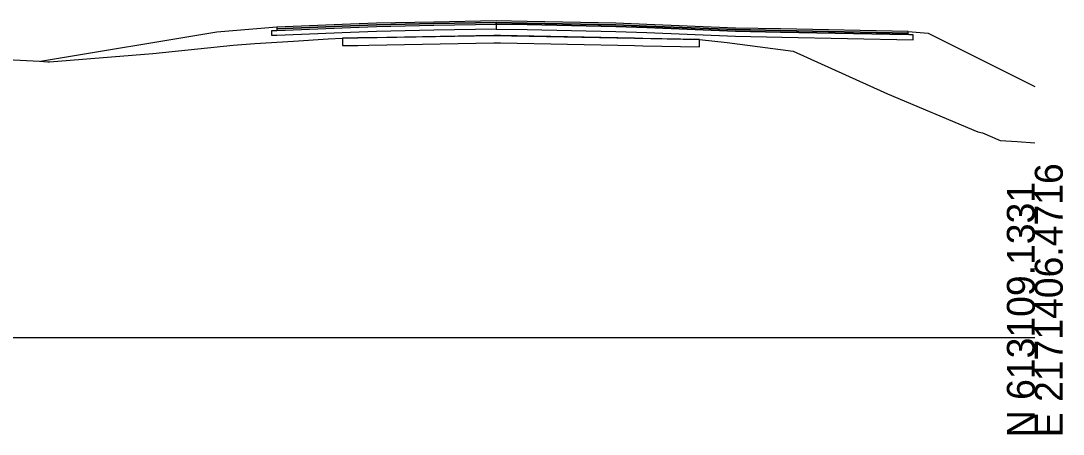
# Model space of a CAD drawing. Extents: x -26 to 1303, y -3010 to 12038.
# Drawn here: x 198.4 to 302.8, y 4490.3 to 4531.8 of the extents above; entities that cross this region are included whole.
import ezdxf

# ---------------------------------------------------------------- set-up
doc = ezdxf.new("R2010")
doc.units = 0
for name, color, linetype in [('RD_GPK_XS_Cell', 7, 'Continuous'), ('RD_XS_Base', 7, 'Continuous'), ('RD_XS_ExGround', 7, 'Continuous'), ('RD_XS_ExPaveRet', 7, 'Continuous'), ('RD_XS_Greenside', 7, 'Continuous'), ('RD_XS_Pave', 7, 'Continuous'), ('RD_XS_PaveOvlay_CP', 7, 'Continuous'), ('RD_XS_TieSlope', 7, 'Continuous')]:
    doc.layers.add(name, color=color, linetype=linetype)

msp = doc.modelspace()

# ---------------------------------------------------------------- linework, layer by layer
at = {"layer": 'RD_GPK_XS_Cell'}
msp.add_line((150, 4500), (300, 4500), dxfattribs=at)
at = {"layer": 'RD_XS_Base'}
for p, q in [((223.5, 4530.79), (223.87, 4530.81)), ((223.5, 4530.66), (223.5, 4530.79)), ((223.5, 4530.29), (223.5, 4530.66)), ((223.87, 4530.81), (224, 4530.81)), ((224, 4530.81), (231.4, 4531.11)), ((231.4, 4531.11), (234, 4531.21)), ((234, 4530.71), (231.4, 4530.61)), ((234, 4531.21), (239.76, 4531.33)), ((239.76, 4530.83), (234, 4530.71)), ((239.76, 4531.33), (246, 4531.45)), ((246, 4530.95), (239.76, 4530.83)), ((246, 4531.57), (246, 4531.61)), ((246, 4531.61), (246, 4531.44)), ((246, 4531.45), (246, 4531.57)), ((246, 4531.45), (246, 4531.45)), ((249.12, 4531.39), (246, 4531.45)), ((246, 4531.45), (246, 4531.45)), ((246, 4531.45), (246, 4531.32)), ((246, 4531.44), (246, 4530.95)), ((246, 4531.32), (246, 4530.95)), ((246, 4530.95), (249.12, 4530.89)), ((258, 4531.21), (249.12, 4531.39)), ((249.12, 4530.89), (258, 4530.71)), ((261.12, 4531.09), (258, 4531.21)), ((258, 4530.71), (261.12, 4530.59)), ((270, 4530.73), (261.12, 4531.09)), ((274.5, 4530.64), (270, 4530.73)), ((287.3, 4530.39), (274.5, 4530.64)), ((223.87, 4530.31), (223.5, 4530.29)), ((224, 4530.31), (223.87, 4530.31)), ((231.4, 4530.61), (224, 4530.31)), ((261.12, 4530.59), (270, 4530.23)), ((270, 4530.23), (274.63, 4530.14)), ((274.63, 4530.14), (287.8, 4529.88)), ((287.43, 4530.38), (287.3, 4530.39)), ((287.8, 4530.38), (287.43, 4530.38)), ((287.8, 4530.25), (287.8, 4530.38)), ((287.8, 4529.88), (287.8, 4530.25))]:
    msp.add_line(p, q, dxfattribs=at)
at = {"layer": 'RD_XS_ExGround'}
msp.add_lwpolyline([(185.28, 4528.49), (200.23, 4527.71), (201.05, 4527.66), (201.16, 4527.66), (201.22, 4527.66), (201.24, 4527.66), (211.57, 4528.5), (219.62, 4529.33), (221.81, 4529.5), (225.67, 4529.72), (229.17, 4529.95), (230.58, 4530.04), (232.13, 4530.06), (245.77, 4530.31), (259.88, 4530.03), (266.4, 4529.9), (269.16, 4529.59), (275.76, 4528.74), (284.87, 4524.62), (285.24, 4524.46), (294.29, 4520.63), (294.75, 4520.52), (296.53, 4519.77), (298.24, 4519.68), (300, 4519.52)], dxfattribs=at)
at = {"layer": 'RD_XS_ExPaveRet'}
msp.add_line((266.4, 4529.9), (260.71, 4530.01), dxfattribs=at)
for points in [[(259.88, 4530.03), (246.42, 4530.3), (245.77, 4530.31), (233.22, 4530.08), (232.13, 4530.06), (230.58, 4530.04), (230.58, 4530.04), (230.58, 4529.98), (230.58, 4529.29), (230.58, 4529.29), (232.13, 4529.31), (233.22, 4529.33), (245.77, 4529.56), (246.42, 4529.55), (259.88, 4529.28), (260.71, 4529.26), (266.4, 4529.15), (266.4, 4529.84), (266.4, 4529.9), (260.71, 4530.01), (259.88, 4530.03)], [(233.22, 4530.08), (232.13, 4530.06), (230.58, 4530.04)], [(230.58, 4530.04), (230.58, 4529.98), (230.58, 4529.29), (232.13, 4529.31), (233.22, 4529.33), (245.77, 4529.56), (246.42, 4529.55), (259.88, 4529.28), (260.71, 4529.26), (266.4, 4529.15), (266.4, 4529.84), (266.4, 4529.9)], [(246.42, 4530.3), (245.77, 4530.31), (233.22, 4530.08)], [(260.71, 4530.01), (259.88, 4530.03), (246.42, 4530.3)]]:
    msp.add_lwpolyline(points, dxfattribs=at)
at = {"layer": 'RD_XS_Greenside'}
for p, q in [((218, 4530.65), (200.32, 4527.7)), ((289.3, 4530.54), (300, 4525.19))]:
    msp.add_line(p, q, dxfattribs=at)
at = {"layer": 'RD_XS_Pave'}
for p, q in [((246, 4531.77), (239.76, 4531.65)), ((249.12, 4531.71), (246, 4531.77)), ((258, 4531.53), (249.12, 4531.71)), ((231.4, 4531.43), (224, 4531.13)), ((231.4, 4531.27), (224, 4530.97)), ((224, 4530.97), (231.4, 4531.27)), ((224, 4531.13), (224, 4531.09)), ((224, 4530.81), (231.4, 4531.11)), ((224, 4531.09), (224, 4530.97)), ((224, 4530.97), (224, 4530.93)), ((224, 4530.93), (224, 4530.81)), ((234, 4531.53), (231.4, 4531.43)), ((234, 4531.37), (231.4, 4531.27)), ((231.4, 4531.27), (234, 4531.37)), ((231.4, 4531.11), (234, 4531.21)), ((239.76, 4531.65), (234, 4531.53)), ((239.76, 4531.49), (234, 4531.37)), ((234, 4531.37), (239.76, 4531.49)), ((234, 4531.21), (239.76, 4531.33)), ((246, 4531.61), (239.76, 4531.49)), ((239.76, 4531.49), (246, 4531.61)), ((239.76, 4531.33), (246, 4531.45)), ((246, 4531.57), (246, 4531.61)), ((246, 4531.61), (249.12, 4531.55)), ((249.12, 4531.55), (246, 4531.61)), ((246, 4531.61), (246, 4531.61)), ((246, 4531.61), (246, 4531.61)), ((246, 4531.61), (246, 4531.57)), ((246, 4531.45), (246, 4531.57)), ((246, 4531.57), (246, 4531.45)), ((246, 4531.45), (246, 4531.45)), ((246, 4531.45), (246, 4531.45)), ((246, 4531.45), (249.12, 4531.39)), ((249.12, 4531.55), (258, 4531.37)), ((258, 4531.37), (249.12, 4531.55)), ((249.12, 4531.39), (258, 4531.21)), ((261.12, 4531.41), (258, 4531.53)), ((258, 4531.37), (261.12, 4531.25)), ((261.12, 4531.25), (258, 4531.37)), ((258, 4531.21), (261.12, 4531.09)), ((270, 4531.05), (261.12, 4531.41)), ((261.12, 4531.25), (270, 4530.89)), ((270, 4530.89), (261.12, 4531.25)), ((261.12, 4531.09), (270, 4530.73)), ((274.5, 4530.96), (270, 4531.05)), ((270, 4530.89), (274.5, 4530.8)), ((274.5, 4530.8), (270, 4530.89)), ((270, 4530.73), (274.5, 4530.64)), ((287.3, 4530.7), (274.5, 4530.96)), ((274.5, 4530.8), (287.3, 4530.55)), ((287.3, 4530.55), (274.5, 4530.8)), ((274.5, 4530.64), (287.3, 4530.39)), ((287.3, 4530.66), (287.3, 4530.7)), ((287.3, 4530.55), (287.3, 4530.66)), ((287.3, 4530.5), (287.3, 4530.55)), ((287.3, 4530.39), (287.3, 4530.5))]:
    msp.add_line(p, q, dxfattribs=at)
at = {"layer": 'RD_XS_PaveOvlay_CP'}
for p, q in [((246, 4531.77), (239.76, 4531.65)), ((249.12, 4531.71), (246, 4531.77)), ((258, 4531.53), (249.12, 4531.71)), ((231.4, 4531.43), (224, 4531.13)), ((234, 4531.53), (231.4, 4531.43)), ((239.76, 4531.65), (234, 4531.53)), ((261.12, 4531.41), (258, 4531.53)), ((270, 4531.05), (261.12, 4531.41)), ((274.5, 4530.96), (270, 4531.05)), ((287.3, 4530.7), (274.5, 4530.96))]:
    msp.add_line(p, q, dxfattribs=at)
at = {"layer": 'RD_XS_TieSlope'}
for p, q in [((224, 4531.13), (218, 4530.65)), ((287.3, 4530.7), (289.3, 4530.54))]:
    msp.add_line(p, q, dxfattribs=at)

# ---------------------------------------------------------------- texts
at = {"layer": 'RD_GPK_XS_Cell'}
for s, p in [('E 2171406.4716', (302.8, 4490)), ('N 613109.1331', (300, 4490))]:
    msp.add_text(s, height=2.8, rotation=90, dxfattribs=at).set_placement(p)

doc.saveas('drawing.dxf')
